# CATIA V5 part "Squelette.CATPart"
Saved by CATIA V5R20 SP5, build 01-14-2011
Part number: Squelette
Publications: "hd", "vd", "hc", "vc", "he", "ve", "hf", "vf", "A", "D", "C", "E", "Plan yz", "Point.5", "Droite.7", "Droite.2", "Droite.3", "Droite.4", "Droite.5", "Droite.71", "Droite.8", "Droite.9", "Rayon_trou_bielle", "Epaisseur_bielle", "Hauteur_bielle", "Rayon_extérieur_bielle", "Plan zx", "Rayon_tige"
Bounding box of the stored display mesh (mm): x -10 to 10, y -100 to 400, z -150 to 150
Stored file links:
  F:\Mini projet IAO\rjugie\Squelette.CATPart
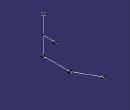
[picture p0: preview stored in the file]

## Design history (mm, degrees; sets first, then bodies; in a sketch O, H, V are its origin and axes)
Parameters
  hd = -100 mm
  vd = -150 mm
  hc = 120 mm
  vc = -150 mm
  he = 400 mm
  ve = -50 mm
  hf = -100 mm
  vf = 150 mm
  Rayon_trou_bielle = 10 mm
  Epaisseur_bielle = 20 mm
  Demi_hauteur_bielle = 15 mm
  `Rayon_extérieur_bâti` = 20 mm
  Rayon_tige = 15 mm
Set1
  Point1 "A": type OnPlane, Support yz-plane, H 0, V 0, Direction (0, 1, 0)
  Point2 "D": type OnPlane, Support yz-plane, H -100 {= hd}, V -150 {= vd}, Direction (0, 1, 0)
  Point3 "C": type OnPlane, Support yz-plane, H 120 {= hc}, V -150 {= vc}, Direction (0, 1, 0)
  Point4 "E": type OnPlane, Support yz-plane, H 400 {= he}, V -50 {= ve}, Direction (0, 1, 0)
  Point5 "F": type OnPlane, Support yz-plane, H -100 {= hf}, V 150 {= vf}, Direction (0, 1, 0)
  Line1 "Droite.7": type PtPt, FirstPoint Point2, SecondPoint Point3
  Line2: type PtPt, FirstPoint Point3, SecondPoint Point4
  Line3: type PtPt, FirstPoint Point5, SecondPoint Point2
  Line4: type PtDir, RefPoint Point1, Direction Line1, Start 0, End -100 {= hd}
  Line5: type Normal, RefPoint Point1, RefSkin yz-plane, Start 10, End -10
  Line6: type PtDir, RefPoint Point2, Direction Line5, Start 10, End -10
  Line7: type PtDir, RefPoint Point3, Direction Line5, Start 10, End -10
  Line8: type PtDir, RefPoint Point4, Direction Line5, Start 10, End -10
Body1 (main body)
